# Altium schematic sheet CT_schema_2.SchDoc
size 282 x 169 mm
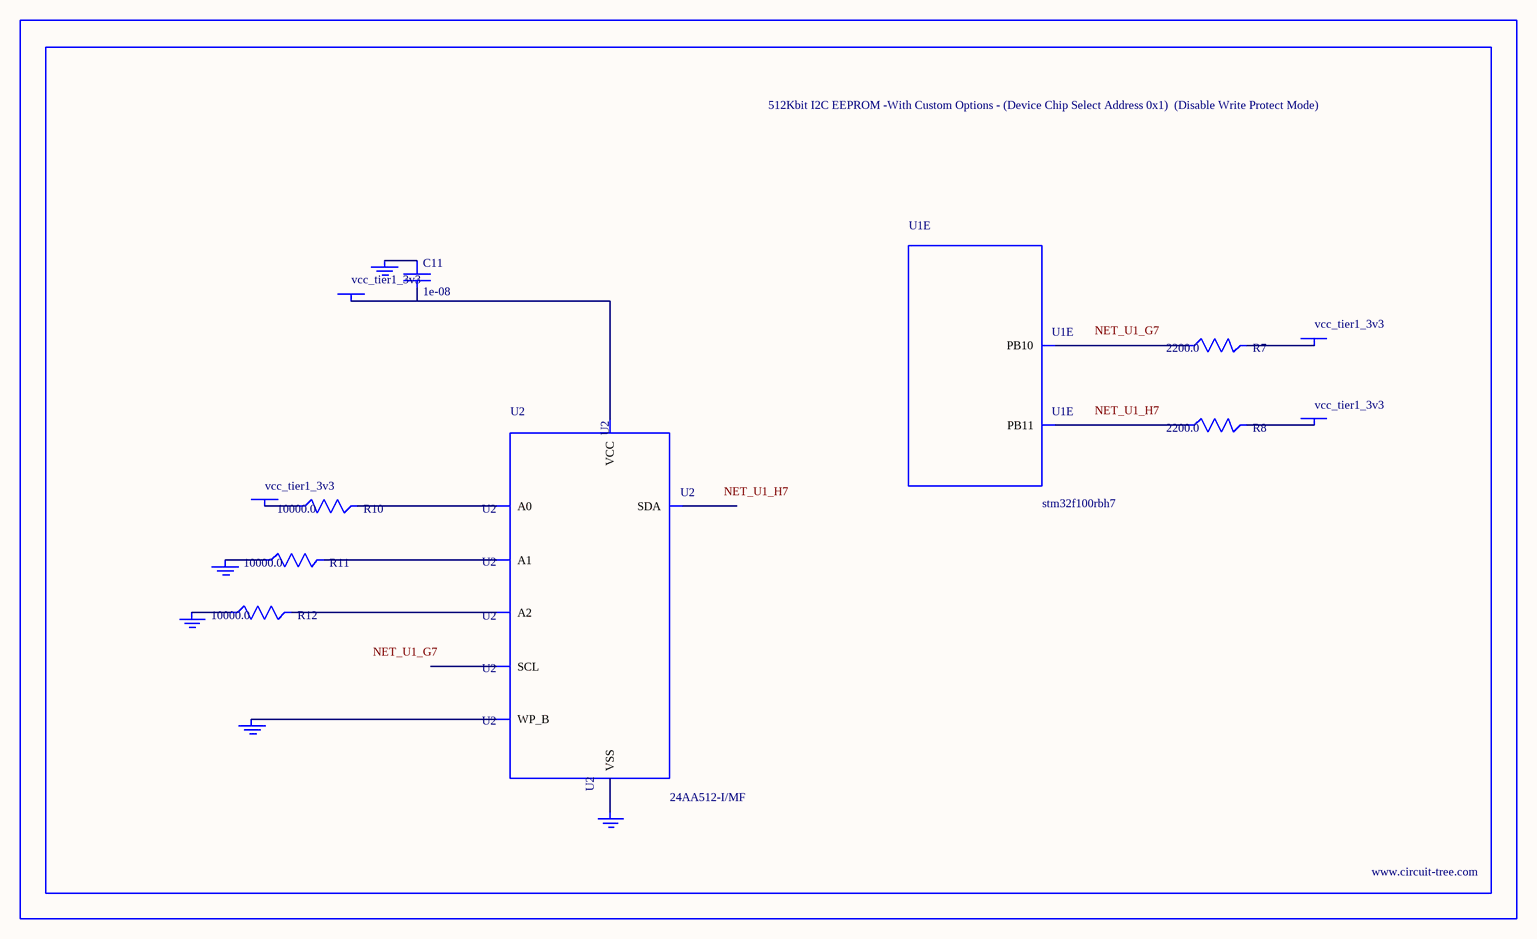
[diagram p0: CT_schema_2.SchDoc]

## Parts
BORDER1  (no value)
C11  1e-08  [C0402]
GND_INSTANCE_1_0  (no value)
GND_INSTANCE_1_1  (no value)
GND_INSTANCE_1_2  (no value)
GND_INSTANCE_1_3  (no value)
GND_INSTANCE_1_4  (no value)
POWER_INSTANCE_1_0  vcc_tier1_3v3
POWER_INSTANCE_1_1  vcc_tier1_3v3
POWER_INSTANCE_1_2  vcc_tier1_3v3
POWER_INSTANCE_1_3  vcc_tier1_3v3
R7  2200.0  [R0603]
R8  2200.0  [R0603]
R10  10000.0  [R0603]
R11  10000.0  [R0603]
R12  10000.0  [R0603]
U1  stm32f100rbh7  [TFBGA64]  (part E of 6)
U2  24AA512-I/MF  [DFN8-S]

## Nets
NetC11_1: C11.1 GND_INSTANCE_1_3.0(GND)
NetC11_2: C11.2 POWER_INSTANCE_1_1.0(PWR) U2.8(VCC)
NetGND_INSTANCE_1_0_0: GND_INSTANCE_1_0.0(GND) R11.1
NetGND_INSTANCE_1_1_0: GND_INSTANCE_1_1.0(GND) R12.1
NetGND_INSTANCE_1_2_0: GND_INSTANCE_1_2.0(GND) U2.7(WP_B)
NetGND_INSTANCE_1_4_0: GND_INSTANCE_1_4.0(GND) U2.4(VSS)
NetPOWER_INSTANCE_1_0_0: POWER_INSTANCE_1_0.0(PWR) R10.1
NetPOWER_INSTANCE_1_2_0: POWER_INSTANCE_1_2.0(PWR) R7.2
NetPOWER_INSTANCE_1_3_0: POWER_INSTANCE_1_3.0(PWR) R8.2
NetR7_1: R7.1 U1.G7(PB10)
NetR8_1: R8.1 U1.H7(PB11)
NetR10_2: R10.2 U2.1(A0)
NetR11_2: R11.2 U2.2(A1)
NetR12_2: R12.2 U2.3(A2)

Not connected (* = marked no-connect by the designer): U2 5(SDA) 6(SCL)

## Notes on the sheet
- Labels drawn without touching a wire or pin: NET_U1_G7, NET_U1_H7

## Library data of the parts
BORDER1 = BORDER_PAGE1
C11 = C0402C103K3RAC
GND_INSTANCE_1_0-GND_INSTANCE_1_4 = GND
POWER_INSTANCE_1_0-POWER_INSTANCE_1_3 = PWR
R7 R8 = RC0603JR-072K2L
R10-R12 = RC0603JR-0710KL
